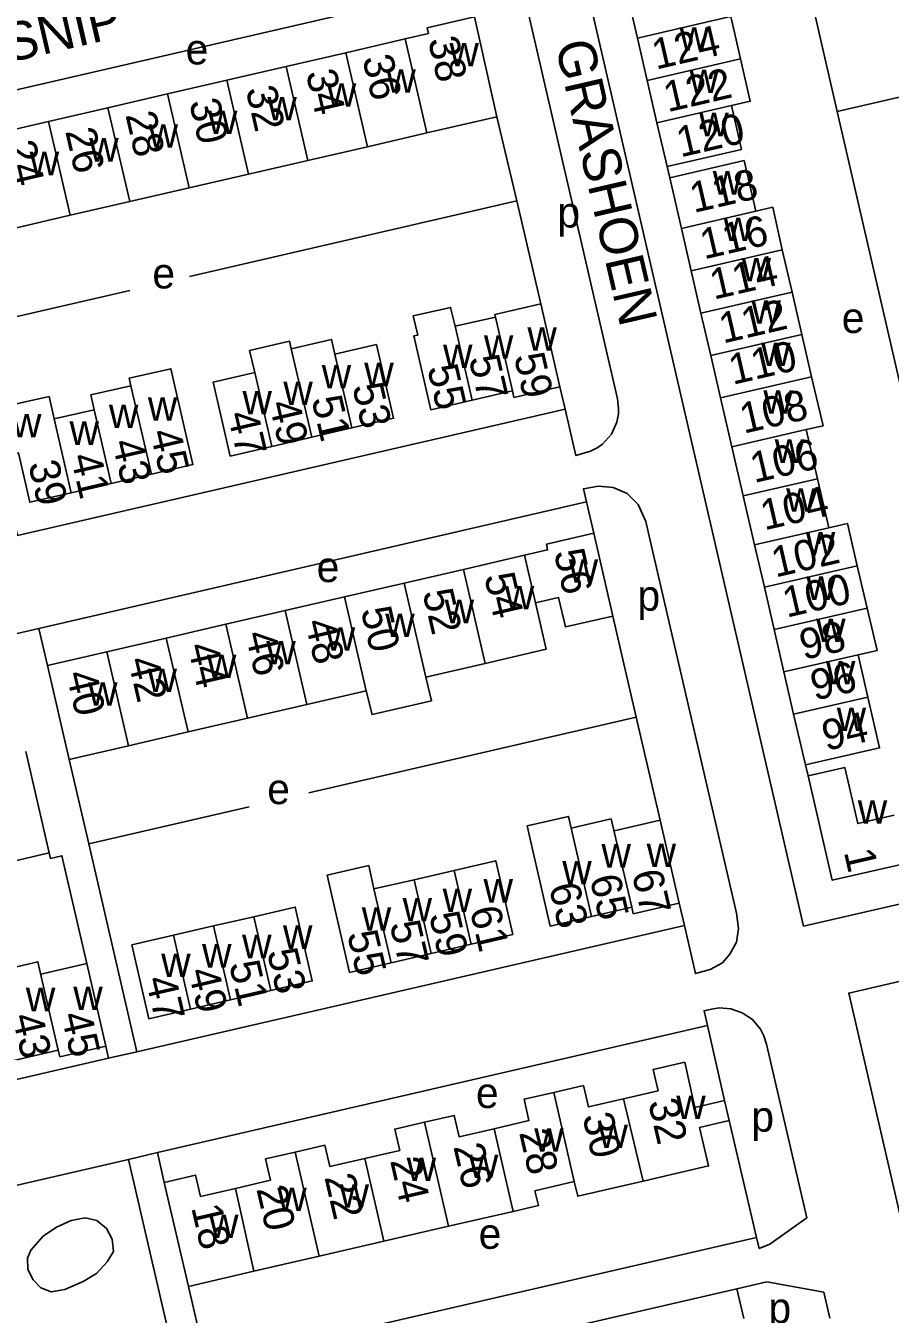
# Model space of a CAD drawing. Extents: x 155696 to 157795, y 382328 to 384028.
# Drawn here: x 156713.8 to 156827.2, y 383346.1 to 383515 of the extents above; entities that cross this region are included whole.
import ezdxf

# ---------------------------------------------------------------- set-up
doc = ezdxf.new("R2010")
doc.units = 0
for name, color, linetype in [('BLT_Basislijn', 7, 'Continuous'), ('BLT_Bebouwing', 7, 'Continuous'), ('BLT_Centroide', 7, 'Continuous'), ('BLT_Huisnummer', 7, 'Continuous'), ('BLT_Huisnummer_ tussenligend', 7, 'Continuous'), ('BLT_Onderverdeling_panden', 7, 'Continuous'), ('BLT_Straatnaam', 7, 'Continuous')]:
    doc.layers.add(name, color=color, linetype=linetype)

msp = doc.modelspace()

# ---------------------------------------------------------------- linework, layer by layer
at = {"layer": 'BLT_Basislijn'}
for p, q in [((156770.41, 383593.43), (156815.79, 383396.96)), ((156811.98, 383539.73), (156820.23, 383503.79)), ((156829.86, 383506.04), (156820.23, 383503.79)), ((156775.59, 383503.08), (156778.22, 383492.06)), ((156837.46, 383428.77), (156820.23, 383503.79)), ((156797.91, 383496.57), (156798.25, 383495.11)), ((156778.22, 383492.06), (156735.27, 383482.14)), ((156727.45, 383480.34), (156706.4, 383475.47)), ((156710.34, 383434.82), (156715.52, 383436.01)), ((156750.91, 383414.42), (156793.87, 383424.35)), ((156816.04, 383418.11), (156816.4, 383416.66)), ((156722.05, 383407.76), (156743.09, 383412.62)), ((156815.79, 383396.96), (156877.29, 383411.17)), ((156689.54, 383400.25), (156716.86, 383406.56)), ((156724.67, 383379.63), (156728.35, 383380.48)), ((156727.27, 383366.37), (156731.07, 383367.25))]:
    msp.add_line(p, q, dxfattribs=at)
for points in [[(156784.53, 383464.78), (156785.94, 383458.68), (156787.86, 383459.24), (156788.72, 383459.67), (156789.44, 383460.17), (156790.62, 383461.48), (156791.31, 383463.06), (156791.54, 383464.15), (156791.55, 383464.86), (156791.4, 383466.13), (156779.47, 383517.75), (156779.12, 383518.86), (156778.68, 383519.62), (156777.7, 383520.79), (156776.27, 383521.8), (156774.84, 383522.26), (156773.28, 383522.38), (156771.28, 383522.11), (156771.7, 383520.32)], [(156699.88, 383503.73), (156771.7, 383520.32)], [(156778.22, 383492.06), (156781.34, 383478.56)], [(156783.85, 383467.7), (156784.52, 383464.78)], [(156784.52, 383464.78), (156712.71, 383448.19), (156710.34, 383458.45)], [(156800.17, 383397.06), (156801.63, 383390.73), (156803.56, 383391.26), (156805.16, 383392.14), (156806.14, 383393.3), (156806.99, 383394.84), (156807.25, 383396.65), (156806.99, 383398.64), (156795.57, 383448.09), (156795.12, 383450.04), (156794.12, 383452.26), (156792.68, 383453.68), (156790.82, 383454.49), (156788.92, 383454.66), (156786.94, 383454.33), (156787.34, 383452.6)], [(156715.52, 383436.01), (156787.34, 383452.6)], [(156787.34, 383452.6), (156788.29, 383448.48)], [(156790.8, 383437.63), (156793.87, 383424.35)], [(156716.64, 383431.14), (156715.52, 383436.01)], [(156793.87, 383424.35), (156796.99, 383410.84)], [(156713.8, 383419.84), (156716.86, 383406.56)], [(156722.05, 383407.76), (156719.49, 383418.82)], [(156800.17, 383397.06), (156728.35, 383380.48), (156722.05, 383407.76)], [(156716.86, 383406.56), (156717.03, 383405.83), (156718.54, 383406.18), (156721.8, 383392.07)], [(156799.49, 383399.99), (156800.17, 383397.06)], [(156831.18, 383347.25), (156821.72, 383388.18), (156849.96, 383394.71)], [(156816.21, 383358.69), (156810.96, 383381.46), (156810.61, 383382.55), (156810.14, 383383.46), (156809.1, 383384.71), (156807.77, 383385.6), (156806.27, 383386.12), (156804.73, 383386.23), (156803.73, 383386.08), (156802.76, 383385.86), (156803.21, 383383.91)], [(156731.07, 383367.25), (156803.21, 383383.91)], [(156803.21, 383383.91), (156805.42, 383374.11)], [(156724.31, 383381.21), (156724.67, 383379.63), (156656.48, 383363.88), (156656.11, 383365.46)], [(156806.04, 383371.48), (156809.62, 383356.14)], [(156731.97, 383363.35), (156731.07, 383367.25)], [(156664.33, 383327.71), (156659.04, 383350.61), (156727.27, 383366.37), (156732.56, 383343.47)], [(156816.21, 383358.69), (156811.36, 383355.26), (156809.96, 383354.68), (156809.62, 383356.14)], [(156809.62, 383356.14), (156737.49, 383339.48), (156735.12, 383349.71)], [(156807.07, 383349.4), (156810.97, 383350.29), (156818.46, 383348.95)], [(156738.84, 383333.63), (156807.07, 383349.4)], [(156807.07, 383349.4), (156807.97, 383345.5)], [(156818.46, 383348.95), (156819.26, 383345.53)]]:
    msp.add_lwpolyline(points, dxfattribs=at)
msp.add_lwpolyline([(156714.47, 383354.47), (156716.1, 383356.3), (156717.84, 383357.48), (156719.77, 383358.33), (156721.57, 383358.7), (156723.14, 383358.35), (156724.38, 383357.31), (156725.13, 383355.89), (156725.3, 383354.28), (156724.46, 383352.91), (156723.07, 383351.42), (156721.33, 383350.35), (156718.91, 383349.28), (156717.15, 383348.98), (156715.76, 383349.51), (156714.76, 383350.59), (156714.09, 383351.92), (156714.01, 383353.4)], close=True, dxfattribs=at)
at = {"layer": 'BLT_Bebouwing'}
for p, q in [((156792.74, 383518.99), (156794.02, 383513.43)), ((156772.65, 383516.2), (156775.59, 383503.08)), ((156755.76, 383511.51), (156763.55, 383513.31)), ((156763.55, 383513.31), (156766.6, 383514.01)), ((156794.02, 383513.43), (156795.3, 383507.88)), ((156747.96, 383509.71), (156755.76, 383511.51)), ((156740.17, 383507.9), (156747.96, 383509.71)), ((156732.37, 383506.1), (156740.17, 383507.9)), ((156795.3, 383507.88), (156796.58, 383502.33)), ((156724.58, 383504.3), (156732.37, 383506.1)), ((156716.78, 383502.5), (156724.58, 383504.3)), ((156708.99, 383500.7), (156716.78, 383502.5)), ((156775.59, 383503.08), (156766.4, 383500.98)), ((156796.58, 383502.33), (156797.91, 383496.57)), ((156758.6, 383499.18), (156750.81, 383497.38)), ((156750.81, 383497.38), (156743.01, 383495.58)), ((156743.01, 383495.58), (156735.22, 383493.78)), ((156798.25, 383495.11), (156799.78, 383488.47)), ((156735.22, 383493.78), (156727.43, 383491.98)), ((156727.43, 383491.98), (156719.63, 383490.18)), ((156719.63, 383490.18), (156711.84, 383488.38)), ((156799.78, 383488.47), (156801.07, 383482.92)), ((156813, 383485.67), (156814.29, 383480.12)), ((156801.07, 383482.92), (156802.35, 383477.36)), ((156783.85, 383467.7), (156781.34, 383478.56)), ((156802.35, 383477.36), (156803.63, 383471.81)), ((156775.38, 383476.84), (156770.12, 383475.63)), ((156759.79, 383473.24), (156754.35, 383471.99)), ((156803.63, 383471.81), (156804.92, 383466.25)), ((156804.92, 383466.25), (156806.4, 383459.82)), ((156717.52, 383463.48), (156722.79, 383464.69)), ((156756.58, 383462.3), (156751.32, 383461.08)), ((156816.15, 383462.07), (156817.63, 383455.64)), ((156751.32, 383461.08), (156746.06, 383459.87)), ((156806.4, 383459.82), (156807.89, 383453.39)), ((156730.29, 383456.22), (156725.02, 383455.01)), ((156817.63, 383455.64), (156819.12, 383449.21)), ((156725.02, 383455.01), (156719.76, 383453.79)), ((156807.89, 383453.39), (156809.37, 383446.96)), ((156788.29, 383448.48), (156790.8, 383437.63)), ((156809.37, 383446.96), (156810.66, 383441.41)), ((156779.19, 383445.59), (156771.21, 383443.74)), ((156763.41, 383441.94), (156771.21, 383443.74)), ((156822.83, 383444.22), (156824.15, 383438.68)), ((156763.41, 383441.94), (156755.62, 383440.15)), ((156747.82, 383438.34), (156755.62, 383440.15)), ((156810.66, 383441.41), (156811.94, 383435.86)), ((156740.03, 383436.55), (156747.82, 383438.34)), ((156732.23, 383434.74), (156740.03, 383436.55)), ((156732.23, 383434.74), (156724.44, 383432.94)), ((156811.94, 383435.86), (156813.22, 383430.3)), ((156716.64, 383431.14), (156724.44, 383432.94)), ((156774.05, 383431.42), (156766.26, 383429.62)), ((156822.96, 383432.55), (156824.25, 383427)), ((156716.64, 383431.14), (156719.49, 383418.82)), ((156813.22, 383430.3), (156814.5, 383424.75)), ((156758.46, 383427.82), (156750.67, 383426.02)), ((156750.67, 383426.02), (156742.88, 383424.22)), ((156814.5, 383424.75), (156816.04, 383418.11)), ((156742.88, 383424.22), (156735.08, 383422.42)), ((156735.08, 383422.42), (156727.29, 383420.61)), ((156727.29, 383420.61), (156719.49, 383418.82)), ((156796.99, 383410.84), (156799.49, 383399.99)), ((156759.46, 383401.84), (156764.73, 383403.05)), ((156764.73, 383403.05), (156769.99, 383404.27)), ((156793.26, 383399.44), (156788, 383398.23)), ((156743.69, 383398.19), (156738.43, 383396.98)), ((156733.17, 383395.76), (156738.43, 383396.98)), ((156772.22, 383394.58), (156766.96, 383393.37)), ((156766.96, 383393.37), (156761.7, 383392.15)), ((156721.8, 383392.07), (156724.31, 383381.21)), ((156740.67, 383387.29), (156745.93, 383388.51)), ((156735.4, 383386.08), (156740.67, 383387.29)), ((156712.23, 383379.32), (156718.07, 383380.67)), ((156735.12, 383349.71), (156731.97, 383363.35))]:
    msp.add_line(p, q, dxfattribs=at)
for points in [[(156772.65, 383516.2), (156766.43, 383514.76), (156766.6, 383514.01)], [(156803.76, 383515.68), (156806.27, 383516.26), (156807.54, 383510.71)], [(156807.54, 383510.71), (156808.82, 383505.15), (156806.33, 383504.58)], [(156806.33, 383504.58), (156807.66, 383498.82), (156797.91, 383496.57)], [(156766.4, 383500.98), (156758.6, 383499.18)], [(156798.25, 383495.11), (156808, 383497.36), (156809.53, 383490.72)], [(156809.53, 383490.72), (156811.76, 383491.24), (156813, 383485.67)], [(156814.29, 383480.12), (156815.57, 383474.57)], [(156770.12, 383475.63), (156769.51, 383478.11), (156764.62, 383476.98), (156765.2, 383474.47), (156764.67, 383474.37)], [(156781.34, 383478.56), (156775.31, 383477.16), (156775.38, 383476.84)], [(156748.62, 383472.69), (156748.4, 383473.66), (156743.15, 383472.45), (156743.82, 383469.55)], [(156754.35, 383471.99), (156753.88, 383473.91), (156748.62, 383472.69)], [(156764.67, 383474.37), (156766.91, 383464.68), (156772.36, 383465.94)], [(156815.57, 383474.57), (156816.85, 383469.01)], [(156759.79, 383473.24), (156762.03, 383463.56), (156756.58, 383462.3)], [(156727.59, 383467.84), (156727.36, 383468.81), (156732.81, 383470.07), (156735.73, 383457.48), (156730.29, 383456.22)], [(156743.82, 383469.55), (156738.38, 383468.3), (156740.61, 383458.61), (156746.06, 383459.87)], [(156816.85, 383469.01), (156818.39, 383462.59), (156816.15, 383462.07)], [(156722.79, 383464.69), (156722.33, 383466.62), (156727.59, 383467.84)], [(156772.36, 383465.94), (156777.62, 383467.16)], [(156777.62, 383467.16), (156777.81, 383466.31), (156783.85, 383467.7)], [(156708.91, 383464.61), (156711.41, 383465.18), (156716.85, 383466.4), (156717.52, 383463.48)], [(156719.76, 383453.79), (156714.32, 383452.54), (156712.83, 383459.02), (156710.34, 383458.45)], [(156779.19, 383445.59), (156782.24, 383446.3), (156782.07, 383447.04), (156788.29, 383448.48)], [(156819.12, 383449.21), (156821.55, 383449.78), (156822.83, 383444.22)], [(156790.8, 383437.63), (156784.58, 383436.19), (156783.68, 383440.05), (156780.64, 383439.34)], [(156780.64, 383439.34), (156782.04, 383433.27), (156774.05, 383431.42)], [(156824.15, 383438.68), (156825.44, 383433.12), (156822.96, 383432.55)], [(156766.26, 383429.62), (156766.99, 383426.51), (156759.22, 383424.7), (156758.46, 383427.82)], [(156824.25, 383427), (156825.78, 383420.36), (156816.04, 383418.11)], [(156816.4, 383416.66), (156821.2, 383417.77), (156822.9, 383410.41), (156827.69, 383411.52)], [(156816.4, 383416.66), (156819.57, 383402.97), (156829.15, 383405.18)], [(156785.32, 383409.82), (156784.97, 383411.35), (156779.55, 383410.1), (156780.32, 383406.65), (156782.55, 383396.97), (156788, 383398.23)], [(156791.02, 383409.13), (156790.57, 383411.03), (156785.32, 383409.82)], [(156796.99, 383410.84), (156790.95, 383409.45), (156791.02, 383409.13)], [(156759.46, 383401.84), (156758.78, 383404.89), (156753.32, 383403.63), (156754.02, 383400.58), (156756.25, 383390.89), (156761.7, 383392.15)], [(156769.99, 383404.27), (156775.43, 383405.53), (156777.67, 383395.84), (156772.22, 383394.58)], [(156743.69, 383398.19), (156749.14, 383399.45), (156751.37, 383389.77), (156745.93, 383388.51)], [(156799.49, 383399.99), (156793.46, 383398.59), (156793.26, 383399.44)], [(156733.17, 383395.76), (156727.72, 383394.5), (156729.96, 383384.82), (156735.4, 383386.08)], [(156709.55, 383390.94), (156715.39, 383392.28), (156715.84, 383390.35)], [(156715.84, 383390.35), (156715.76, 383390.67), (156721.8, 383392.07)], [(156718.07, 383380.67), (156718.27, 383379.82), (156724.31, 383381.21)], [(156792.17, 383374.31), (156796.75, 383375.37), (156796.1, 383378.16), (156800.21, 383379.11), (156801.53, 383373.19), (156805.42, 383374.11)], [(156783.05, 383375.15), (156786.94, 383376.05), (156787.59, 383373.25), (156792.17, 383374.31)], [(156775.21, 383370.39), (156779.79, 383371.45), (156779.15, 383374.25), (156783.05, 383375.15)], [(156805.42, 383374.11), (156806.04, 383371.48)], [(156758.26, 383366.48), (156762.84, 383367.54), (156762.19, 383370.33), (156766.09, 383371.23)], [(156766.09, 383371.23), (156769.99, 383372.13), (156770.64, 383369.34), (156775.21, 383370.39)], [(156806.04, 383371.48), (156802.16, 383370.57), (156803.35, 383365.5), (156794.78, 383363.49)], [(156741.31, 383362.56), (156745.89, 383363.62), (156745.24, 383366.42), (156749.14, 383367.32)], [(156749.14, 383367.32), (156753.04, 383368.22), (156753.68, 383365.42), (156758.26, 383366.48)], [(156731.97, 383363.35), (156736.08, 383364.3), (156736.73, 383361.5), (156741.31, 383362.56)], [(156785.74, 383363.46), (156780.57, 383362.26), (156781.02, 383360.31), (156777.72, 383359.55)], [(156794.78, 383363.49), (156786.18, 383361.53), (156785.74, 383363.46)], [(156777.72, 383359.55), (156769.23, 383357.61)], [(156769.23, 383357.61), (156760.77, 383355.64)], [(156760.77, 383355.64), (156752.26, 383353.69)], [(156752.26, 383353.69), (156747.12, 383352.48), (156743.71, 383351.69)], [(156743.71, 383351.69), (156735.12, 383349.71)]]:
    msp.add_lwpolyline(points, dxfattribs=at)
at = {"layer": 'BLT_Onderverdeling_panden'}
for p, q in [((156794.02, 383513.43), (156803.76, 383515.68)), ((156763.55, 383513.31), (156766.4, 383500.98)), ((156755.76, 383511.51), (156758.6, 383499.18)), ((156747.96, 383509.71), (156750.81, 383497.38)), ((156795.3, 383507.88), (156807.54, 383510.71)), ((156740.17, 383507.9), (156743.01, 383495.58)), ((156732.37, 383506.1), (156735.22, 383493.78)), ((156724.58, 383504.3), (156727.43, 383491.98)), ((156796.58, 383502.33), (156806.33, 383504.58)), ((156716.78, 383502.5), (156719.63, 383490.18)), ((156799.78, 383488.47), (156809.53, 383490.72)), ((156801.07, 383482.92), (156813, 383485.67)), ((156802.35, 383477.36), (156814.29, 383480.12)), ((156770.12, 383475.63), (156772.36, 383465.94)), ((156775.38, 383476.84), (156777.62, 383467.16)), ((156803.63, 383471.81), (156815.57, 383474.57)), ((156748.62, 383472.69), (156751.32, 383461.08)), ((156754.35, 383471.99), (156756.58, 383462.3)), ((156743.82, 383469.55), (156746.06, 383459.87)), ((156804.92, 383466.25), (156816.85, 383469.01)), ((156727.59, 383467.84), (156730.29, 383456.22)), ((156717.52, 383463.48), (156719.76, 383453.79)), ((156722.79, 383464.69), (156725.02, 383455.01)), ((156806.4, 383459.82), (156816.15, 383462.07)), ((156807.89, 383453.39), (156817.63, 383455.64)), ((156809.37, 383446.96), (156819.12, 383449.21)), ((156779.19, 383445.59), (156780.64, 383439.34)), ((156771.21, 383443.74), (156774.05, 383431.42)), ((156810.66, 383441.41), (156822.83, 383444.22)), ((156763.41, 383441.94), (156766.26, 383429.62)), ((156755.62, 383440.15), (156758.46, 383427.82)), ((156747.82, 383438.34), (156750.67, 383426.02)), ((156811.94, 383435.86), (156824.15, 383438.68)), ((156740.03, 383436.55), (156742.88, 383424.22)), ((156732.23, 383434.74), (156735.08, 383422.42)), ((156724.44, 383432.94), (156727.29, 383420.61)), ((156813.22, 383430.3), (156822.96, 383432.55)), ((156814.5, 383424.75), (156824.25, 383427)), ((156785.32, 383409.82), (156788, 383398.23)), ((156791.02, 383409.13), (156793.26, 383399.44)), ((156764.73, 383403.05), (156766.96, 383393.37)), ((156769.99, 383404.27), (156772.22, 383394.58)), ((156759.46, 383401.84), (156761.7, 383392.15)), ((156743.69, 383398.19), (156745.93, 383388.51)), ((156738.43, 383396.98), (156740.67, 383387.29)), ((156733.17, 383395.76), (156735.4, 383386.08)), ((156715.84, 383390.35), (156718.07, 383380.67)), ((156783.05, 383375.15), (156785.74, 383363.46)), ((156792.17, 383374.31), (156794.78, 383363.49)), ((156766.09, 383371.23), (156769.23, 383357.61)), ((156775.21, 383370.39), (156777.72, 383359.55)), ((156749.14, 383367.32), (156752.26, 383353.69)), ((156758.26, 383366.48), (156760.77, 383355.64)), ((156741.31, 383362.56), (156743.71, 383351.69))]:
    msp.add_line(p, q, dxfattribs=at)

# ---------------------------------------------------------------- texts
at = {"layer": 'BLT_Centroide'}
for s, p in [('w', (156799.53, 383511.78)), ('e', (156734.77, 383509.97)), ('w', (156769.36, 383509.72)), ('w', (156761.08, 383506.25)), ('w', (156800.82, 383506.22)), ('w', (156753.28, 383504.44)), ('w', (156745.48, 383502.64)), ('w', (156737.69, 383500.84)), ('w', (156802.12, 383500.56)), ('w', (156729.91, 383499.05)), ('w', (156722.11, 383497.23)), ('w', (156714.31, 383495.44)), ('w', (156803.89, 383492.91)), ('p', (156783.52, 383488.58)), ('w', (156805.3, 383486.81)), ('w', (156807.68, 383481.53)), ('e', (156730.4, 383480.59)), ('w', (156808.96, 383475.97)), ('e', (156820.81, 383474.75)), ('w', (156779.58, 383472.44)), ('w', (156773.88, 383471.39)), ('w', (156768.52, 383470.16)), ('w', (156810.24, 383470.41)), ('w', (156752.61, 383467.5)), ('w', (156758.19, 383467.77)), ('w', (156742.22, 383464.08)), ('w', (156747.58, 383465.31)), ('w', (156810.53, 383464.16)), ('w', (156724.7, 383462.27)), ('w', (156729.81, 383463.24)), ('w', (156711.99, 383461.06)), ('w', (156719.54, 383460.07)), ('w', (156812.02, 383457.72)), ('w', (156813.51, 383451.31)), ('w', (156816.1, 383445.59)), ('e', (156751.95, 383442.08)), ('w', (156785, 383442)), ('w', (156776.62, 383438.5)), ('w', (156816.16, 383439.75)), ('p', (156794.02, 383438.33)), ('w', (156768.73, 383436.69)), ('w', (156760.94, 383434.88)), ('w', (156817.45, 383434.22)), ('w', (156753.14, 383433.08)), ('w', (156745.34, 383431.28)), ('w', (156737.55, 383429.48)), ('w', (156818.73, 383428.66)), ('w', (156729.77, 383427.67)), ('w', (156721.97, 383425.88)), ('w', (156820.15, 383422.56)), ('e', (156745.47, 383412.96)), ('w', (156822.91, 383410.38)), ('w', (156789.3, 383404.64)), ('w', (156795.22, 383404.72)), ('w', (156784.16, 383402.44)), ('w', (156773.83, 383400.05)), ('w', (156768.47, 383398.81)), ('w', (156757.86, 383396.36)), ('w', (156763.22, 383397.59)), ('w', (156747.53, 383393.98)), ('w', (156736.92, 383391.53)), ('w', (156742.17, 383392.75)), ('w', (156731.56, 383390.28)), ('w', (156713.81, 383385.8)), ('w', (156720.03, 383385.94)), ('e', (156772.84, 383373.1)), ('w', (156799.11, 383371.67)), ('p', (156808.95, 383370)), ('w', (156788.91, 383367.86)), ('w', (156780.48, 383367.38)), ('w', (156763.75, 383363.52)), ('w', (156771.91, 383363.92)), ('w', (156746.78, 383359.59)), ('w', (156754.95, 383360.02)), ('w', (156737.84, 383356.05)), ('e', (156773.19, 383354.64)), ('p', (156811.2, 383344.9))]:
    msp.add_text(s, height=4, dxfattribs=at).set_placement(p)
at = {"layer": 'BLT_Huisnummer'}
for s, rotation, p in [('124', 13.0064, (156796.44, 383509.28)), ('38', 283.0058, (156766.52, 383513.18)), ('34', 283.0058, (156750.51, 383508.88)), ('30', 283.0058, (156735.21, 383505.05)), ('120', 13.0064, (156799.66, 383497.77)), ('26', 283.0058, (156718.96, 383501.22)), ('118', 13.0064, (156801.4, 383490.48)), ('114', 13.0064, (156804.03, 383479.11)), ('110', 13.0064, (156806.51, 383467.94)), ('59', 283.0086, (156777.8, 383471.7)), ('55', 283.0086, (156766.43, 383470.19)), ('49', 283.0086, (156745.7, 383465.5)), ('51', 283.0086, (156751.25, 383466.09)), ('43', 283.0086, (156725.11, 383460.41)), ('106', 13.0064, (156809.32, 383455.06)), ('41', 283.0086, (156719.66, 383458.56)), ('102', 13.0064, (156812.11, 383442.67)), ('56', 283.0041, (156783.04, 383445.99)), ('52', 283.0041, (156765.81, 383440.75)), ('48', 283.0041, (156750.41, 383436.84)), ('98', 13.0064, (156815.81, 383431.85)), ('44', 283.0041, (156735.01, 383433.71)), ('40', 283.0041, (156719.08, 383430.05)), ('94', 13.0064, (156818.75, 383419.92)), ('1', 283.007, (156821.07, 383406.69)), ('67', 283.0465, (156793.25, 383403.92)), ('63', 283.0465, (156782.39, 383402.19)), ('61', 283.0465, (156772.01, 383399.14)), ('55', 283.0465, (156755.92, 383395.96)), ('53', 283.0465, (156745.42, 383393.6)), ('47', 283.0465, (156729.49, 383389.99)), ('45', 283.0465, (156718.42, 383385.29)), ('32', 283.0091, (156795.4, 383373.89)), ('28', 283.0091, (156778.48, 383369.89)), ('26', 283.0091, (156769.86, 383368.05)), ('22', 283.0091, (156752.95, 383364.04)), ('18', 283.0091, (156735.48, 383360.07))]:
    msp.add_text(s, height=4, rotation=rotation, dxfattribs=at).set_placement(p)
at = {"layer": 'BLT_Huisnummer_ tussenligend'}
for s, rotation, p in [('36', 283.0058, (156757.92, 383510.79)), ('122', 13.0064, (156797.97, 383503.69)), ('32', 283.0058, (156742.62, 383506.71)), ('28', 283.0058, (156726.85, 383503.37)), ('24', 283.0058, (156711.07, 383499.55)), ('116', 13.0064, (156802.75, 383484.39)), ('112', 13.0064, (156805.24, 383473.36)), ('57', 283.0086, (156771.88, 383471.43)), ('53', 283.0086, (156756.6, 383467.75)), ('108', 13.0064, (156807.95, 383461.53)), ('47', 283.0086, (156740.24, 383464.09)), ('45', 283.0086, (156730.09, 383461.73)), ('39', 283.0086, (156714.11, 383457.6)), ('104', 13.0064, (156810.67, 383448.85)), ('54', 283.0041, (156773.9, 383442.86)), ('100', 13.0064, (156813.58, 383437.4)), ('50', 283.0041, (156757.72, 383438.42)), ('46', 283.0041, (156742.58, 383435.28)), ('42', 283.0041, (156727.18, 383431.87)), ('96', 13.0064, (156817.24, 383426.52)), ('65', 283.0465, (156787.73, 383403.28)), ('57', 283.0465, (156761.5, 383397.24)), ('59', 283.0465, (156766.66, 383398.41)), ('49', 283.0465, (156735.1, 383391.07)), ('51', 283.0465, (156740.45, 383391.99)), ('43', 283.0465, (156712, 383385.11)), ('30', 283.0091, (156786.78, 383372.05)), ('24', 283.0091, (156761.56, 383366.21)), ('20', 283.0091, (156744.02, 383362.51))]:
    msp.add_text(s, height=4, rotation=rotation, dxfattribs=at).set_placement(p)
at = {"layer": 'BLT_Straatnaam'}
for s, rotation, p in [('GRASSNIP', 13.0063, (156693.12, 383505.93)), ('GRASHOEN', 283.0057, (156783.21, 383512.62))]:
    msp.add_text(s, height=5, rotation=rotation, dxfattribs=at).set_placement(p)

doc.saveas('drawing.dxf')
